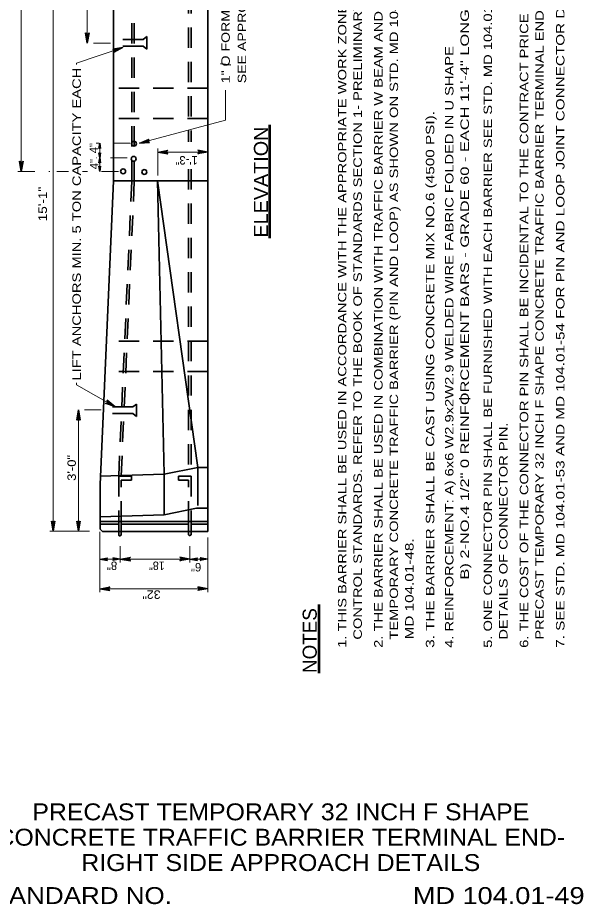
# Model space of a CAD drawing. Extents: x 12.6 to 19.5, y 6.1 to 16.3.
# Drawn here: x 15.52 to 19.53, y 6.05 to 12.35 of the extents above; entities that cross this region are included whole.
import ezdxf
from ezdxf.enums import TextEntityAlignment as Align

# ---------------------------------------------------------------- set-up
doc = ezdxf.new("R2010")
doc.units = 0
doc.header["$LTSCALE"] = 0.024
doc.linetypes.add('DOT_DASHED', pattern=[7.7, 5, -1.2, 0.3, -1.2])
doc.linetypes.add('LONG_DASHED', pattern=[7.5, 6, -1.5])
for name, color, linetype, lineweight in [('1', 7, 'Continuous', 35), ('10', 7, 'Continuous', 25), ('12', 7, 'Continuous', 53), ('13', 7, 'Continuous', 53)]:
    doc.layers.add(name, color=color, linetype=linetype, lineweight=lineweight)

msp = doc.modelspace()

# ---------------------------------------------------------------- hatches: boundary and pattern name
at = {"layer": '10'}
for points in [[(16.0222, 12.24), (16.0096, 12.1685), (15.997, 12.24), (16.0096, 12.2265)], [(16.191, 12.1249), (16.2628, 12.1359), (16.1991, 12.101), (16.2079, 12.1173)], [(16.0915, 11.4207), (16.0978, 11.4564), (16.1041, 11.4207), (16.0978, 11.4274)], [(16.4524, 11.4628), (16.3801, 11.4564), (16.4459, 11.4871), (16.4361, 11.4714)], [(16.5811, 11.3822), (16.5096, 11.3948), (16.5811, 11.4074), (16.5676, 11.3948)], [(16.7949, 11.4074), (16.8664, 11.3948), (16.7949, 11.3822), (16.8084, 11.3948)], [(15.5533, 11.329), (15.5407, 11.2575), (15.5281, 11.329), (15.5407, 11.3155)], [(16.1041, 11.3883), (16.0978, 11.3526), (16.0915, 11.3883), (16.0978, 11.3816)], [(16.0915, 11.3169), (16.0978, 11.3526), (16.1041, 11.3169), (16.0978, 11.3236)], [(16.1041, 11.2932), (16.0978, 11.2575), (16.0915, 11.2932), (16.0978, 11.2865)], [(16.1506, 9.6321), (16.2064, 9.5856), (16.1381, 9.6102), (16.1561, 9.6144)], [(15.9342, 9.4924), (15.9468, 9.5639), (15.9594, 9.4924), (15.9468, 9.5059)], [(15.7798, 8.7744), (15.7672, 8.7029), (15.7546, 8.7744), (15.7672, 8.7609)], [(15.9594, 8.7744), (15.9468, 8.7029), (15.9342, 8.7744), (15.9468, 8.7609)], [(16.1529, 8.4956), (16.0993, 8.505), (16.1529, 8.5144), (16.1428, 8.505)], [(16.1903, 8.5144), (16.2439, 8.505), (16.1903, 8.4956), (16.2004, 8.505)], [(16.3154, 8.4924), (16.2439, 8.505), (16.3154, 8.5176), (16.3019, 8.505)], [(16.6669, 8.5176), (16.7384, 8.505), (16.6669, 8.4924), (16.6804, 8.505)], [(16.792, 8.4956), (16.7384, 8.505), (16.792, 8.5144), (16.7819, 8.505)], [(16.8121, 8.5144), (16.8657, 8.505), (16.8121, 8.4956), (16.8222, 8.505)], [(16.1708, 8.282), (16.0993, 8.2946), (16.1708, 8.3072), (16.1573, 8.2946)], [(16.7942, 8.3072), (16.8657, 8.2946), (16.7942, 8.282), (16.8077, 8.2946)]]:
    msp.add_hatch(color=256, dxfattribs=at).paths.add_polyline_path(points)

# ---------------------------------------------------------------- linework, layer by layer
at = {"layer": '1'}
for p, q in [((16.8664, 13.032), (16.8664, 8.7006)), ((16.7947, 9.1553), (16.5075, 11.1894)), ((16.5553, 9.1074), (16.5075, 11.1894)), ((16.7947, 9.1553), (16.5553, 9.1074)), ((16.8664, 9.1553), (16.7947, 9.1553)), ((16.7947, 8.8866), (16.7947, 9.1553)), ((16.5553, 9.1074), (16.1011, 9.0928)), ((16.5553, 8.8203), (16.5553, 9.1074)), ((16.5553, 8.8203), (16.1011, 8.8056)), ((16.7861, 8.8664), (16.5553, 8.8203)), ((16.8652, 8.8664), (16.7861, 8.8664)), ((16.1006, 8.7723), (16.8664, 8.7723)), ((16.1006, 8.7535), (16.2324, 8.7535)), ((16.2324, 8.6854), (16.2324, 8.7723)), ((16.25, 8.6759), (16.25, 8.7723)), ((16.25, 8.7535), (16.7293, 8.7535)), ((16.7293, 8.6772), (16.7293, 8.7723)), ((16.747, 8.6776), (16.747, 8.7726)), ((16.8664, 8.7535), (16.747, 8.7535)), ((16.1006, 8.7186), (16.1186, 8.7006)), ((16.1186, 8.7006), (16.2096, 8.7006)), ((16.2055, 8.7006), (16.7323, 8.7006)), ((16.2324, 8.6745), (16.2324, 8.6868)), ((16.25, 8.6759), (16.25, 8.6868)), ((16.8664, 8.7006), (16.7216, 8.7006))]:
    msp.add_line(p, q, dxfattribs=at)
at = {"layer": '1', "linetype": 'LONG_DASHED'}
for p, q in [((16.3256, 11.1894), (16.3256, 13.0105)), ((16.3431, 11.1894), (16.3431, 13.0105)), ((16.7293, 13.0105), (16.7293, 11.4668)), ((16.747, 13.0105), (16.747, 11.4668)), ((16.4062, 12.1938), (16.4323, 12.2144)), ((16.4323, 12.126), (16.4323, 12.2144)), ((16.4062, 12.1944), (16.1964, 12.1944)), ((16.4062, 12.1466), (16.1964, 12.1466)), ((16.4062, 12.1466), (16.4323, 12.126)), ((16.8664, 11.8475), (16.1964, 11.8475)), ((16.8664, 11.632), (16.1964, 11.632)), ((16.7293, 11.2733), (16.7293, 9.0945)), ((16.747, 11.2733), (16.747, 9.0945)), ((16.2324, 9.0942), (16.3256, 11.1894)), ((16.2499, 9.0942), (16.3431, 11.1894)), ((16.8664, 10.0527), (16.1458, 10.0527)), ((16.8664, 9.8373), (16.1363, 9.8373)), ((16.3328, 9.5861), (16.1251, 9.5861)), ((16.3328, 9.5853), (16.3589, 9.606)), ((16.3589, 9.5175), (16.3589, 9.606)), ((16.3328, 9.5382), (16.123, 9.5382)), ((16.3328, 9.5382), (16.3589, 9.5175))]:
    msp.add_line(p, q, dxfattribs=at)
at = {"layer": '1'}
for points in [[(16.1964, 13.014), (16.1964, 11.1894), (16.8664, 11.1894)], [(16.1006, 8.7186), (16.1006, 9.0357), (16.1964, 11.1894)]]:
    msp.add_lwpolyline(points, dxfattribs=at)
at = {"layer": '1', "linetype": 'LONG_DASHED'}
for points in [[(16.2499, 8.772), (16.2499, 9.0651), (16.323, 9.0651), (16.323, 9.0942), (16.2324, 9.0942), (16.2324, 8.7723)], [(16.7293, 8.7723), (16.7293, 9.0654), (16.6564, 9.0654), (16.6564, 9.0945), (16.747, 9.0945), (16.747, 8.7726)]]:
    msp.add_lwpolyline(points, dxfattribs=at)
at = {"layer": '1'}
for centre in [(16.34139, 11.45431), (16.33921, 11.3462), (16.2638, 11.25751), (16.41466, 11.25316)]:
    msp.add_circle(centre, 0.01746, dxfattribs=at)
for centre, start, end in [((16.24092, 8.67995), 212.34561, 334.49396), ((16.73814, 8.68232), 209.85794, 332.34078)]:
    msp.add_arc(centre, 0.01003, start, end, dxfattribs=at)
at = {"layer": '10', "lineweight": 13}
for p, q in [((15.5407, 13.0342), (15.5407, 11.2575)), ((15.7672, 8.7029), (15.7672, 13.0342)), ((16.0096, 12.1685), (16.0096, 13.0342)), ((15.9337, 12.0244), (16.2628, 12.1359)), ((15.9337, 12.0244), (15.9337, 12.0169)), ((16.0978, 11.4564), (16.0978, 11.3526)), ((16.5096, 11.2279), (16.5096, 11.4198)), ((16.5096, 11.3948), (16.8664, 11.3948)), ((16.0978, 11.2575), (16.0978, 11.3526)), ((15.9337, 9.7566), (15.9337, 9.7419)), ((15.9337, 9.7419), (16.2064, 9.5856)), ((15.9468, 8.7029), (15.9468, 9.5639)), ((16.0254, 8.7029), (15.7422, 8.7029)), ((16.0993, 8.6991), (16.0993, 8.2696)), ((16.8657, 8.6592), (16.8657, 8.2696)), ((16.2439, 8.5975), (16.2439, 8.48)), ((16.7384, 8.5975), (16.7384, 8.48)), ((16.2439, 8.505), (16.0993, 8.505)), ((16.2439, 8.505), (16.7384, 8.505)), ((16.8657, 8.505), (16.7384, 8.505)), ((16.8657, 8.2946), (16.0993, 8.2946))]:
    msp.add_line(p, q, dxfattribs=at)
at = {"layer": '10'}
for p, q in [((16.0096, 12.1685), (15.997, 12.24)), ((16.0096, 12.1685), (16.0222, 12.24)), ((16.2628, 12.1359), (16.191, 12.1249)), ((16.2628, 12.1359), (16.1991, 12.101)), ((17.0293, 12.0105), (16.9549, 12.0213)), ((16.0978, 11.4564), (16.0915, 11.4207)), ((16.0978, 11.4564), (16.1041, 11.4207)), ((16.3801, 11.4564), (16.4459, 11.4871)), ((16.3801, 11.4564), (16.4524, 11.4628)), ((16.5096, 11.3948), (16.5811, 11.4074)), ((16.5096, 11.3948), (16.5811, 11.3822)), ((16.8664, 11.3948), (16.7949, 11.4074)), ((16.8664, 11.3948), (16.7949, 11.3822)), ((15.5407, 11.2575), (15.5281, 11.329)), ((15.5407, 11.2575), (15.5533, 11.329)), ((16.0978, 11.3526), (16.0915, 11.3883)), ((16.0978, 11.3526), (16.0915, 11.3169)), ((16.0978, 11.3526), (16.1041, 11.3883)), ((16.0978, 11.3526), (16.1041, 11.3169)), ((16.0978, 11.2575), (16.0915, 11.2932)), ((16.0978, 11.2575), (16.1041, 11.2932)), ((16.2064, 9.5856), (16.1506, 9.6321)), ((16.2064, 9.5856), (16.1381, 9.6102)), ((15.9468, 9.5639), (15.9342, 9.4924)), ((15.9468, 9.5639), (15.9594, 9.4924)), ((15.7672, 8.7029), (15.7546, 8.7744)), ((15.7672, 8.7029), (15.7798, 8.7744)), ((15.9468, 8.7029), (15.9342, 8.7744)), ((15.9468, 8.7029), (15.9594, 8.7744)), ((16.0993, 8.505), (16.1529, 8.5144)), ((16.0993, 8.505), (16.1529, 8.4956)), ((16.2439, 8.505), (16.1903, 8.5144)), ((16.2439, 8.505), (16.1903, 8.4956)), ((16.2439, 8.505), (16.3154, 8.5176)), ((16.2439, 8.505), (16.3154, 8.4924)), ((16.7384, 8.505), (16.6669, 8.5176)), ((16.7384, 8.505), (16.6669, 8.4924)), ((16.7384, 8.505), (16.792, 8.5144)), ((16.7384, 8.505), (16.792, 8.4956)), ((16.8657, 8.505), (16.8121, 8.5144)), ((16.8657, 8.505), (16.8121, 8.4956)), ((16.0993, 8.2946), (16.1708, 8.3072)), ((16.8657, 8.2946), (16.7942, 8.3072)), ((16.0993, 8.2946), (16.1708, 8.282)), ((16.8657, 8.2946), (16.7942, 8.282))]:
    msp.add_line(p, q, dxfattribs=at)
at = {"layer": '10', "linetype": 'DOT_DASHED', "lineweight": 13}
for p, q in [((16.174, 12.1685), (15.9846, 12.1685)), ((16.3133, 11.4564), (16.0728, 11.4564)), ((16.2939, 11.3526), (16.0728, 11.3526)), ((15.5157, 11.2575), (15.7422, 11.2575)), ((15.7922, 11.2575), (15.8758, 11.2575)), ((16.2314, 11.2575), (15.9765, 11.2575)), ((16.1091, 9.5639), (15.9218, 9.5639))]:
    msp.add_line(p, q, dxfattribs=at)
at = {"layer": '10'}
for points in [[(16.0222, 12.24), (16.0096, 12.2265), (15.997, 12.24)], [(16.191, 12.1249), (16.2079, 12.1173), (16.1991, 12.101)], [(16.4524, 11.4628), (16.4361, 11.4714), (16.4459, 11.4871)], [(16.0915, 11.4207), (16.0978, 11.4274), (16.1041, 11.4207)], [(16.5811, 11.3822), (16.5676, 11.3948), (16.5811, 11.4074)], [(16.7949, 11.4074), (16.8084, 11.3948), (16.7949, 11.3822)], [(15.5533, 11.329), (15.5407, 11.3155), (15.5281, 11.329)], [(16.1041, 11.3883), (16.0978, 11.3816), (16.0915, 11.3883)], [(16.0915, 11.3169), (16.0978, 11.3236), (16.1041, 11.3169)], [(16.1041, 11.2932), (16.0978, 11.2865), (16.0915, 11.2932)], [(16.1506, 9.6321), (16.1561, 9.6144), (16.1381, 9.6102)], [(15.9342, 9.4924), (15.9468, 9.5059), (15.9594, 9.4924)], [(15.7798, 8.7744), (15.7672, 8.7609), (15.7546, 8.7744)], [(15.9594, 8.7744), (15.9468, 8.7609), (15.9342, 8.7744)], [(16.1529, 8.4956), (16.1428, 8.505), (16.1529, 8.5144)], [(16.1903, 8.5144), (16.2004, 8.505), (16.1903, 8.4956)], [(16.3154, 8.4924), (16.3019, 8.505), (16.3154, 8.5176)], [(16.6669, 8.5176), (16.6804, 8.505), (16.6669, 8.4924)], [(16.792, 8.4956), (16.7819, 8.505), (16.792, 8.5144)], [(16.8121, 8.5144), (16.8222, 8.505), (16.8121, 8.4956)], [(16.1708, 8.282), (16.1573, 8.2946), (16.1708, 8.3072)], [(16.7942, 8.3072), (16.8077, 8.2946), (16.7942, 8.282)]]:
    msp.add_lwpolyline(points, dxfattribs=at)
for points in [[(16.0222, 12.24), (16.0096, 12.1685), (15.997, 12.24), (16.0096, 12.2265)], [(16.191, 12.1249), (16.2628, 12.1359), (16.1991, 12.101), (16.2079, 12.1173)], [(16.0915, 11.4207), (16.0978, 11.4564), (16.1041, 11.4207), (16.0978, 11.4274)], [(16.4524, 11.4628), (16.3801, 11.4564), (16.4459, 11.4871), (16.4361, 11.4714)], [(16.5811, 11.3822), (16.5096, 11.3948), (16.5811, 11.4074), (16.5676, 11.3948)], [(16.7949, 11.4074), (16.8664, 11.3948), (16.7949, 11.3822), (16.8084, 11.3948)], [(15.5533, 11.329), (15.5407, 11.2575), (15.5281, 11.329), (15.5407, 11.3155)], [(16.1041, 11.3883), (16.0978, 11.3526), (16.0915, 11.3883), (16.0978, 11.3816)], [(16.0915, 11.3169), (16.0978, 11.3526), (16.1041, 11.3169), (16.0978, 11.3236)], [(16.1041, 11.2932), (16.0978, 11.2575), (16.0915, 11.2932), (16.0978, 11.2865)], [(16.1506, 9.6321), (16.2064, 9.5856), (16.1381, 9.6102), (16.1561, 9.6144)], [(15.9342, 9.4924), (15.9468, 9.5639), (15.9594, 9.4924), (15.9468, 9.5059)], [(15.7798, 8.7744), (15.7672, 8.7029), (15.7546, 8.7744), (15.7672, 8.7609)], [(15.9594, 8.7744), (15.9468, 8.7029), (15.9342, 8.7744), (15.9468, 8.7609)], [(16.1529, 8.4956), (16.0993, 8.505), (16.1529, 8.5144), (16.1428, 8.505)], [(16.1903, 8.5144), (16.2439, 8.505), (16.1903, 8.4956), (16.2004, 8.505)], [(16.3154, 8.4924), (16.2439, 8.505), (16.3154, 8.5176), (16.3019, 8.505)], [(16.6669, 8.5176), (16.7384, 8.505), (16.6669, 8.4924), (16.6804, 8.505)], [(16.792, 8.4956), (16.7384, 8.505), (16.792, 8.5144), (16.7819, 8.505)], [(16.8121, 8.5144), (16.8657, 8.505), (16.8121, 8.4956), (16.8222, 8.505)], [(16.1708, 8.282), (16.0993, 8.2946), (16.1708, 8.3072), (16.1573, 8.2946)], [(16.7942, 8.3072), (16.8657, 8.2946), (16.7942, 8.282), (16.8077, 8.2946)]]:
    msp.add_lwpolyline(points, close=True, dxfattribs=at)
at = {"layer": '10', "lineweight": 13}
msp.add_lwpolyline([(16.9921, 11.8328), (16.9921, 11.6207), (16.3801, 11.4564)], dxfattribs=at)
at = {"layer": '12'}
msp.add_line((17.3059, 10.7833), (17.3059, 11.5889), dxfattribs=at)
at = {"layer": '13', "lineweight": 25}
msp.add_line((18.6524, 9.6455), (18.7306, 9.6455), dxfattribs=at)
at = {"layer": '13'}
msp.add_line((17.657, 7.6963), (17.657, 8.1836), dxfattribs=at)

# ---------------------------------------------------------------- texts
at = {"layer": '12'}
for s, rotation, width, p in [('1" O FORMED BOLT HOLES', 90, 1.25, (17.0221, 11.8828)), ('SEE APPROACH END VIEW', 90, 1.25, (17.1383, 11.8828)), ('15\'-1"', 90, 1.2, (15.7225, 10.9028)), ('3\'-0"', 90, 1.15, (15.9284, 9.0608)), ('18"', 180, 0.95, (16.5599, 8.4875)), ('32"', 180, 1.1, (16.5306, 8.2829))]:
    msp.add_text(s, height=0.06, rotation=rotation, dxfattribs=dict(at, width=width)).set_placement(p)
for s, height, width, p in [('LIFT ANCHORS MIN. 5 TON CAPACITY EACH', 0.06, 1.3, (15.9637, 10.88325)), ('ELEVATION', 0.1, 1.05, (17.2933, 11.1814))]:
    msp.add_text(s, height=height, rotation=90, dxfattribs=dict(at, width=width)).set_placement(p, align=Align.CENTER)
for s, rotation, p in [('4"', 90, (16.0858, 11.3855)), ('4"', 90, (16.0883, 11.2721)), ('1\'-3"', 180, (16.7951, 11.3658)), ('8"', 180, (16.2219, 8.4876)), ('6"', 180, (16.8192, 8.4775))]:
    msp.add_text(s, height=0.06, rotation=rotation, dxfattribs=at).set_placement(p)
at = {"layer": '13'}
for s, width, p in [('  PRECAST TEMPORARY 32 INCH F SHAPE CONCRETE TRAFFIC BARRIER TERMINAL END RIGHT SIDE APPROACH.', 1.3, (19.2527, 7.8752)), ('6. THE COST OF THE CONNECTOR PIN SHALL BE INCIDENTAL TO THE CONTRACT PRICE PER EACH FOR', 1.3, (19.1427, 7.8752)), ('  TEMPORARY CONCRETE TRAFFIC BARRIER (PIN AND LOOP) AS SHOWN ON STD. MD 104.01-47 AND', 1.3, (18.2177, 7.8752)), ('1. THIS BARRIER SHALL BE USED IN ACCORDANCE WITH THE APPROPRIATE WORK ZONE TRAFFIC', 1.3, (17.8504, 7.8752)), ('2. THE BARRIER SHALL BE USED IN COMBINATION WITH TRAFFIC BARRIER W BEAM AND PRECAST', 1.3, (18.1077, 7.8752)), ('5. ONE CONNECTOR PIN SHALL BE FURNISHED WITH EACH BARRIER SEE STD. MD 104.01-54 FOR', 1.3, (18.8854, 7.8752)), ('7. SEE STD. MD 104.01-53 AND MD 104.01-54 FOR PIN AND LOOP JOINT CONNECTOR DETAILS.', 1.35, (19.4, 7.8752)), ('  CONTROL STANDARDS. REFER TO THE BOOK OF STANDARDS SECTION 1- PRELIMINARY.', 1.3, (17.9604, 7.8752)), ('               B) 2-NO.4 1/2" 0 REINFORCEMENT BARS - GRADE 60 - EACH 11\'-4" LONG', 1.45, (18.7212, 7.8752)), ('4. REINFORCEMENT: A) 6x6 W2.9x2W2.9 WELDED WIRE FABRIC FOLDED IN U SHAPE', 1.3, (18.6112, 7.8752)), ('3. THE BARRIER SHALL BE CAST USING CONCRETE MIX NO.6 (4500 PSI).', 1.35, (18.475, 7.8752)), ('  DETAILS OF CONNECTOR PIN.', 1.3, (18.9954, 7.8752)), ('  MD 104.01-48.', 1.35, (18.3277, 7.8752))]:
    msp.add_text(s, height=0.06, rotation=90, dxfattribs=dict(at, width=width)).set_placement(p)
msp.add_text('NOTES', height=0.1, rotation=90, dxfattribs=at).set_placement((17.6398, 7.6963))
for s, width, p in [('PRECAST TEMPORARY 32 INCH F SHAPE', 1.1, (17.38445, 6.6509)), ('CONCRETE TRAFFIC BARRIER TERMINAL END-', 1.1, (17.3845, 6.4709)), ('RIGHT SIDE APPROACH DETAILS', 1.1, (17.3844, 6.2909)), ('STANDARD NO.', 1.15, (15.9135, 6.0565)), ('MD 104.01-49', 1.2, (18.9327, 6.0565))]:
    msp.add_text(s, height=0.12, dxfattribs=dict(at, width=width)).set_placement(p, align=Align.CENTER)

doc.saveas('drawing.dxf')
